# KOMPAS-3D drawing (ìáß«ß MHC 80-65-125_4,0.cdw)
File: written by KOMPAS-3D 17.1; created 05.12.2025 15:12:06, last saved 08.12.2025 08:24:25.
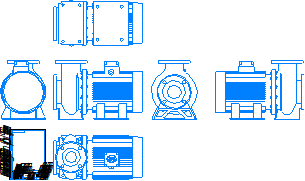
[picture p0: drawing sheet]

Sheet 1: A4, portrait

Title block, sheet 1: name: Насос MHC / 80-65-125_4,0; material: Сталь 10  ГОСТ 1050-88; mass: 163,07; sheets: 1; sheet format: A4; stored path: \\adlc.lan\data\АДЛ_ПКД\3D-модели\ADL production\Насосы ГРАНПАМП\Насосы ГРАНПАМП серии МНС\KOMPAS 2D\Насос MHC 80-65-125_4,0.cdw

Views: Проекционный вид 2, Проекционный вид 3, Проекционный вид 4, Проекционный вид 5, Проекционный вид 6
Referenced files in \\adlc.lan\data\АДЛ_ПКД\3D-модели\ADL production\Насосы ГРАНПАМП\Насосы ГРАНПАМП серии МНС\KOMPAS 3D\: Насос МНС 80-65-125_4,0.m3d
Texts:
  Andrey
  АДЛ
Dimensions and other numbers on the sheet: 1:1; 1; 80-65-125_4,0; 163,07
